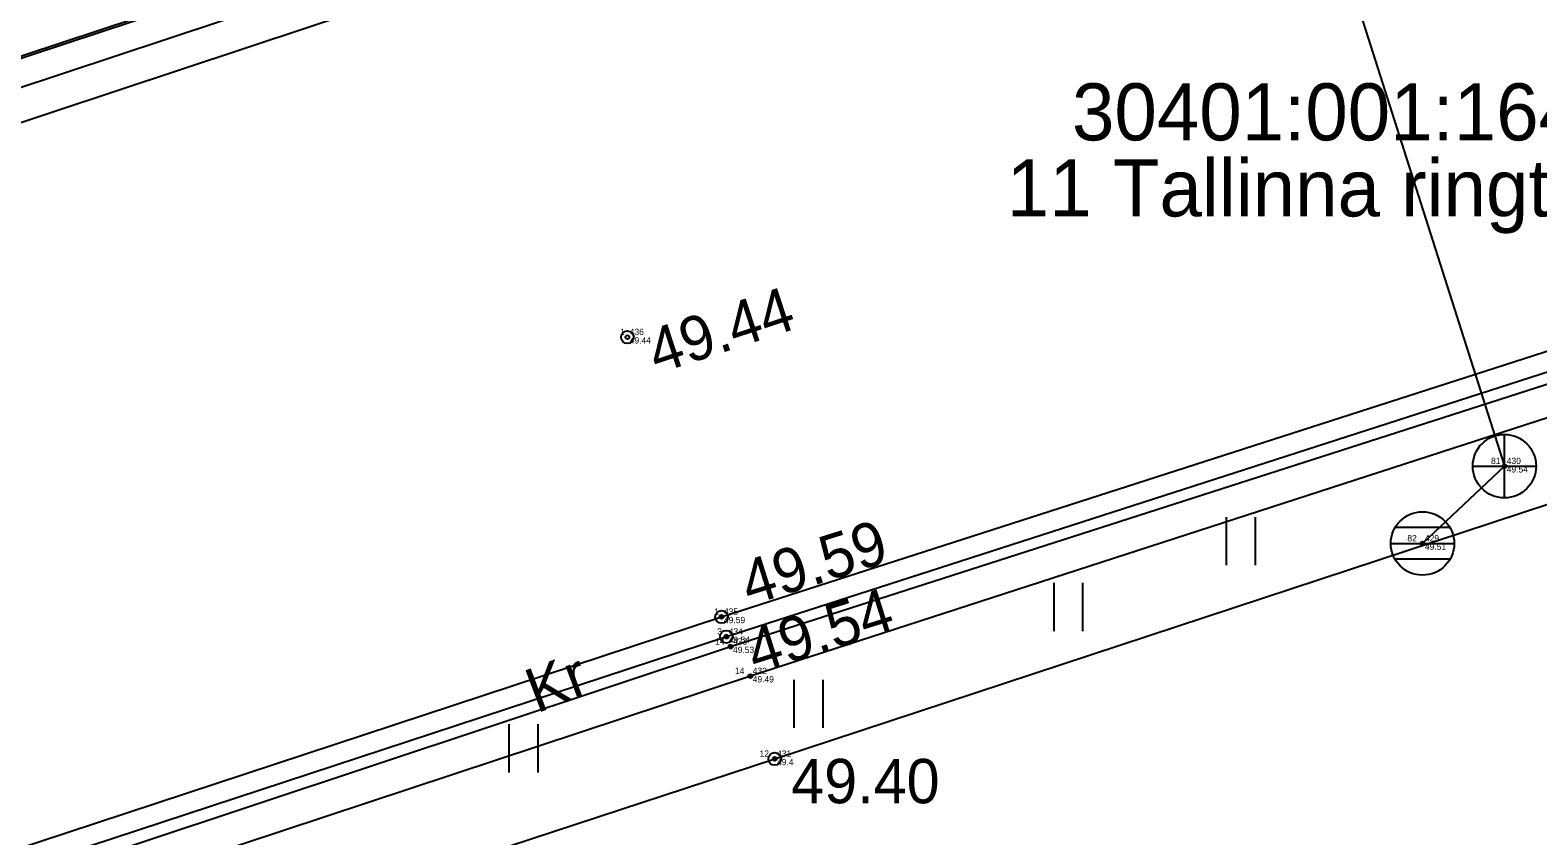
# Model space of a CAD drawing. Extents: x 543497 to 552146, y 6567125 to 6579845.
# Drawn here: x 546016.89 to 546040.67, y 6577663.23 to 6577675.95 of the extents above; entities that cross this region are included whole.
import ezdxf

# ---------------------------------------------------------------- set-up
doc = ezdxf.new("R2010")
doc.units = 0
for name, color, linetype in [('xref_Kangru tee 1_geodeesia$0$HALJASTUS', 7, 'Continuous'), ('xref_Kangru tee 1_geodeesia$0$korgus-EH2000', 7, 'Continuous'), ('xref_Kangru tee 1_geodeesia$0$Liiklus', 7, 'Continuous'), ('xref_Kangru tee 1_geodeesia$0$mootkood', 7, 'Continuous'), ('xref_Kangru tee 1_geodeesia$0$MOOTKORG-eh2000', 7, 'Continuous'), ('xref_Kangru tee 1_geodeesia$0$mootmpunkt', 7, 'Continuous'), ('xref_Kangru tee 1_geodeesia$0$MOOTNR', 7, 'Continuous'), ('xref_Kangru tee 1_geodeesia$0$MOOTPIIR', 7, 'Continuous'), ('xref_Kangru tee 1_geodeesia$0$PIIR', 7, 'Continuous'), ('xref_Kangru tee 1_geodeesia$0$SKKAEV', 7, 'Continuous'), ('xref_Kangru tee 1_geodeesia$0$SKTRASS', 7, 'Continuous'), ('xref_Kangru tee 1_geodeesia$0$TEE', 7, 'Continuous')]:
    doc.layers.add(name, color=color, linetype=linetype)

# ---------------------------------------------------------------- blocks, each defined once
blk = doc.blocks.new('xref_Kangru tee 1_geodeesia$0$REKAEV')
for p, q in [((0.86, 0.5), (-0.86, 0.5)), ((-1, 0), (1, 0)), ((0.86, -0.5), (-0.86, -0.5))]:
    blk.add_line(p, q)
blk.add_circle((0, 0), 1)
blk = doc.blocks.new('xref_Kangru tee 1_geodeesia$0$KAKAEV')
for p, q in [((0, -1), (0, 1)), ((-1, 0), (1, 0))]:
    blk.add_line(p, q)
blk.add_circle((0, 0), 1)
blk = doc.blocks.new('xref_Kangru tee 1_geodeesia$0$hein')
for p, q in [((-0.455, 0.761), (-0.455, -0.761)), ((0.455, 0.761), (0.455, -0.761))]:
    blk.add_line(p, q)

msp = doc.modelspace()

# ---------------------------------------------------------------- linework, layer by layer
at = {"layer": 'xref_Kangru tee 1_geodeesia$0$korgus-EH2000'}
for centre in [(546026.31, 6577671.102), (546027.796, 6577666.689), (546027.872, 6577666.376), (546028.634, 6577664.448)]:
    msp.add_circle(centre, 0.1, dxfattribs=at)
at = {"layer": 'xref_Kangru tee 1_geodeesia$0$Liiklus'}
for points in [[(546140.1, 6577713.825), (546117.037, 6577707.038), (546094.195, 6577700.083), (546071.336, 6577693.084), (546048.1, 6577685.746), (546023.804, 6577677.834), (545999.945, 6577669.953), (545974.62, 6577661.424), (545953.584, 6577654.176), (545929.781, 6577645.689), (545906.69, 6577637.378)], [(546140.387, 6577713.403), (546116.908, 6577706.504), (546094.508, 6577699.709), (546071.341, 6577692.568), (546048.377, 6577685.322), (546024.051, 6577677.467), (546000.007, 6577669.497), (545974.577, 6577660.93), (545953.828, 6577653.707), (545929.813, 6577645.16), (545906.85, 6577636.866)], [(545910.777, 6577625.663), (545933.969, 6577634.025), (545958.008, 6577642.491), (545978.611, 6577649.687), (546003.506, 6577658.099), (546027.939, 6577666.219), (546052.189, 6577674.015), (546074.504, 6577681.116), (546097.636, 6577688.197), (546120.931, 6577695.189), (546144.399, 6577702.07)], [(546144.547, 6577701.652), (546121.068, 6577694.663), (546097.922, 6577687.788), (546074.601, 6577680.633), (546052.33, 6577673.558), (546028.25, 6577665.754), (546003.455, 6577657.552), (545979.103, 6577649.278), (545958.136, 6577642.016), (545934.298, 6577633.553), (545911.013, 6577625.148)]]:
    msp.add_lwpolyline(points, dxfattribs=at)
at = {"layer": 'xref_Kangru tee 1_geodeesia$0$mootmpunkt'}
for centre in [(546026.31, 6577671.102), (546040.147, 6577669.067), (546038.855, 6577667.847), (546027.796, 6577666.689), (546027.872, 6577666.376), (546027.939, 6577666.219), (546028.25, 6577665.754), (546028.634, 6577664.448)]:
    msp.add_circle(centre, 0.03, dxfattribs=at)
at = {"layer": 'xref_Kangru tee 1_geodeesia$0$MOOTPIIR'}
msp.add_lwpolyline([(545958.425, 6577640.634), (545979.717, 6577647.979), (546003.803, 6577656.298), (546028.634, 6577664.448), (546052.642, 6577672.359), (546075.012, 6577679.254), (546098.282, 6577686.38), (546121.547, 6577693.442), (546145.064, 6577700.183), (546144.756, 6577701.079), (546144.547, 6577701.652), (546144.399, 6577702.07), (546144.343, 6577702.205), (546144.19, 6577702.591), (546142.487, 6577707.254), (546140.733, 6577712.948), (546140.387, 6577713.403), (546140.081, 6577713.851), (546139.866, 6577714.146), (546138.846, 6577717.098), (546138.679, 6577717.517), (546137.781, 6577720.873), (546135.39, 6577726.178), (546132.125, 6577738.465)], dxfattribs=at)
at = {"layer": 'xref_Kangru tee 1_geodeesia$0$SKTRASS'}
msp.add_lwpolyline([(546035.169, 6577684.706), (546040.147, 6577669.067), (546038.855, 6577667.847)], dxfattribs=at)
at = {"layer": 'xref_Kangru tee 1_geodeesia$0$TEE'}
for points in [[(545906.85, 6577636.866), (545929.889, 6577645.059), (545953.872, 6577653.571), (545974.605, 6577661.456), (545999.934, 6577669.987), (546023.789, 6577677.871), (546048.093, 6577685.795), (546071.324, 6577693.114), (546094.183, 6577700.122), (546117.024, 6577707.078), (546140.081, 6577713.851)], [(545907.046, 6577636.431), (545930.044, 6577644.691), (545953.99, 6577653.148), (545974.87, 6577660.403), (546000.141, 6577668.988), (546024.289, 6577677), (546048.596, 6577684.894), (546071.539, 6577692.067), (546094.678, 6577699.21), (546117.101, 6577706.011), (546140.733, 6577712.948)], [(545910.584, 6577626.12), (545933.661, 6577634.352), (545957.791, 6577642.935), (545978.471, 6577649.978), (546003.394, 6577658.646), (546027.796, 6577666.689), (546052.06, 6577674.499), (546074.348, 6577681.538), (546097.453, 6577688.664), (546120.761, 6577695.678), (546144.19, 6577702.591)], [(546144.343, 6577702.205), (546120.903, 6577695.427), (546097.566, 6577688.331), (546074.414, 6577681.298), (546052.115, 6577674.191), (546027.872, 6577666.376), (546003.492, 6577658.359), (545978.595, 6577649.764), (545957.931, 6577642.653), (545933.808, 6577634.136), (545910.722, 6577625.792)]]:
    msp.add_lwpolyline(points, dxfattribs=at)

# ---------------------------------------------------------------- block references
at = {"layer": 'xref_Kangru tee 1_geodeesia$0$HALJASTUS', "xscale": 0.5, "yscale": 0.5}
for p in [(546035.986, 6577667.884), (546033.264, 6577666.845), (546029.165, 6577665.317), (546024.668, 6577664.614)]:
    msp.add_blockref('xref_Kangru tee 1_geodeesia$0$hein', p, dxfattribs=at)
at = {"layer": 'xref_Kangru tee 1_geodeesia$0$SKKAEV', "xscale": 0.5, "yscale": 0.5}
for name, p in [('xref_Kangru tee 1_geodeesia$0$KAKAEV', (546040.147, 6577669.067)), ('xref_Kangru tee 1_geodeesia$0$REKAEV', (546038.855, 6577667.847))]:
    msp.add_blockref(name, p, dxfattribs=at)

# ---------------------------------------------------------------- texts
at = {"layer": 'xref_Kangru tee 1_geodeesia$0$korgus-EH2000'}
for s, rotation, p in [(' 49.44 ', 18.1268, (546026.528, 6577670.437)), (' 49.59 ', 17.5658, (546027.988, 6577666.783)), (' 49.54 ', 17.4566, (546028.082, 6577665.708))]:
    msp.add_text(s, height=0.7, rotation=rotation, dxfattribs=at).set_placement(p)
msp.add_text(' 49.40 ', height=0.7, dxfattribs=at).set_placement((546028.634, 6577663.748))
at = {"layer": 'xref_Kangru tee 1_geodeesia$0$mootkood'}
for s, p in [(' 1', (546026.158, 6577671.135)), (' 81', (546039.899, 6577669.1)), (' 82', (546038.579, 6577667.88)), (' 1', (546027.644, 6577666.722)), (' 3', (546027.691, 6577666.409)), (' 14', (546027.658, 6577666.252)), (' 14', (546027.969, 6577665.787)), (' 12', (546028.358, 6577664.481))]:
    msp.add_text(s, height=0.1, dxfattribs=at).set_placement(p)
at = {"layer": 'xref_Kangru tee 1_geodeesia$0$MOOTKORG-eh2000'}
for s, p in [(' 49.44', (546026.31, 6577671.002)), (' 49.54', (546040.147, 6577668.967)), (' 49.51', (546038.855, 6577667.747)), (' 49.59', (546027.796, 6577666.589)), (' 49.54', (546027.872, 6577666.276)), (' 49.53', (546027.939, 6577666.119)), (' 49.49', (546028.25, 6577665.654)), (' 49.4', (546028.634, 6577664.348))]:
    msp.add_text(s, height=0.1, dxfattribs=at).set_placement(p)
at = {"layer": 'xref_Kangru tee 1_geodeesia$0$MOOTNR'}
for s, p in [(' 436', (546026.31, 6577671.135)), (' 430', (546040.147, 6577669.1)), (' 429', (546038.855, 6577667.88)), (' 435', (546027.796, 6577666.722)), (' 434', (546027.872, 6577666.409)), (' 433', (546027.939, 6577666.252)), (' 432', (546028.25, 6577665.787)), (' 431', (546028.634, 6577664.481))]:
    msp.add_text(s, height=0.1, dxfattribs=at).set_placement(p)
at = {"layer": 'xref_Kangru tee 1_geodeesia$0$PIIR'}
for s, p in [('30401:001:1646', (546033.325, 6577674.207)), ('11 Tallinna ringtee', (546032.296, 6577673.007))]:
    msp.add_text(s, height=0.9, dxfattribs=at).set_placement(p)
at = {"layer": 'xref_Kangru tee 1_geodeesia$0$TEE'}
msp.add_text('Kr', height=0.7, rotation=20.6097, dxfattribs=at).set_placement((546024.878, 6577665.163))

doc.saveas('drawing.dxf')
